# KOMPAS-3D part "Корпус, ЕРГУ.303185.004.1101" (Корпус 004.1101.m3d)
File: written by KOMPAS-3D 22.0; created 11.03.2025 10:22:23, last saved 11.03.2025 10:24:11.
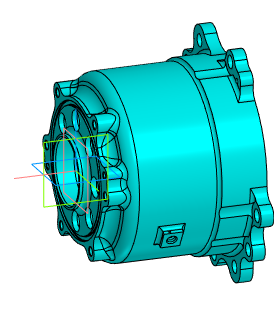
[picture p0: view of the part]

Document properties: Автор: User; Полное имя файла: C:\Users\User\Desktop\Корпус 004.1101.m3d

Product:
- Part/product: Корпус  | designation ЕРГУ.303185.004.1101
    Масса: 2.37924

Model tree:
1. Операция без истории:1

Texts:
  ЕРГУ.303185.004.1101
